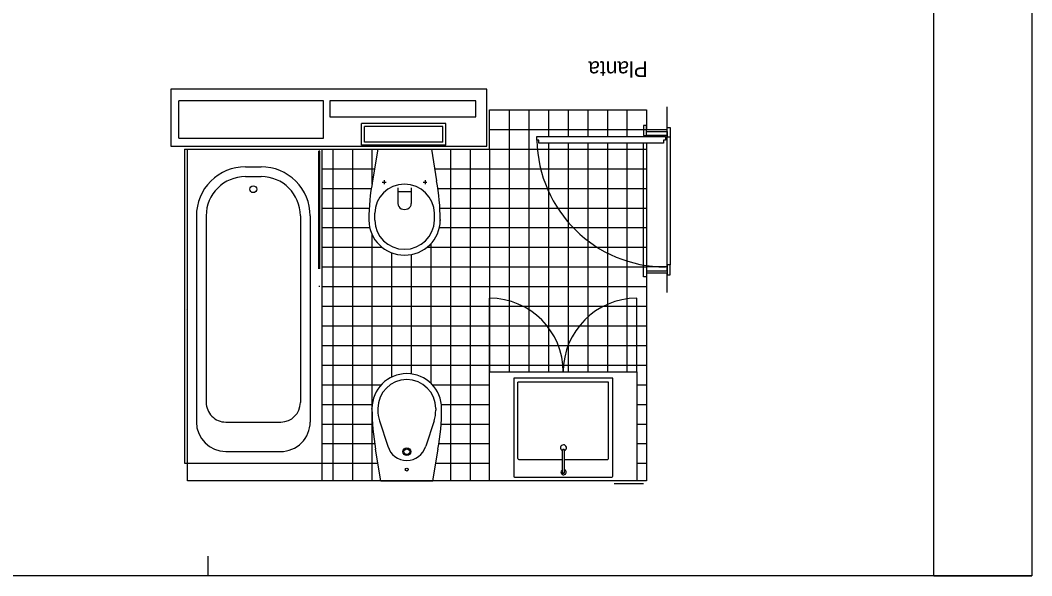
# Model space of a CAD drawing. Extents: x 1289.5 to 1301.1, y -287.4 to -281.5.
# Drawn here: x 1295.93 to 1301.09, y -287.45 to -284.62 of the extents above; entities that cross this region are included whole.
import ezdxf

# ---------------------------------------------------------------- set-up
doc = ezdxf.new("R2010")
doc.units = 0
for name, color, linetype in [('Level 1', 7, 'Continuous'), ('Level 10', 7, 'Continuous'), ('Level 11', 7, 'Continuous'), ('Level 13', 7, 'Continuous'), ('Level 2', 7, 'Continuous'), ('Level 36', 7, 'Continuous'), ('Level 4', 7, 'Continuous'), ('Level 60', 7, 'Continuous'), ('Level 62', 7, 'Continuous')]:
    doc.layers.add(name, color=color, linetype=linetype)

msp = doc.modelspace()

# ---------------------------------------------------------------- linework, layer by layer
at = {"layer": 'Level 1'}
for p, q in [((1298.3115, -284.9706), (1296.7015, -284.9706)), ((1296.7015, -284.9706), (1296.7015, -285.2606)), ((1298.3115, -285.2606), (1298.3115, -284.9706)), ((1296.7415, -285.2206), (1296.7415, -285.0306)), ((1297.4794, -285.0306), (1296.7415, -285.0306)), ((1297.4794, -285.2206), (1297.4794, -285.0306)), ((1297.5115, -285.0306), (1297.5115, -285.1106)), ((1298.2565, -285.0306), (1297.5115, -285.0306)), ((1298.2565, -285.1106), (1298.2565, -285.0306)), ((1298.3265, -285.2756), (1298.3265, -285.0756)), ((1298.3265, -285.0756), (1299.1265, -285.0756)), ((1299.1265, -285.0756), (1299.1265, -285.1756)), ((1299.2315, -285.1756), (1299.2315, -285.0606)), ((1297.5115, -285.1106), (1298.2565, -285.1106)), ((1299.1265, -285.1756), (1299.2315, -285.1756)), ((1296.7015, -285.2606), (1298.3115, -285.2606)), ((1296.7415, -285.2206), (1297.4794, -285.2206)), ((1296.7865, -286.9656), (1296.7865, -285.2756)), ((1296.7865, -285.2756), (1298.3265, -285.2756)), ((1299.1265, -285.9056), (1299.1265, -286.9656)), ((1299.1265, -285.9056), (1299.1365, -285.9056)), ((1299.1265, -285.9056), (1299.2315, -285.9056)), ((1299.2215, -285.9056), (1299.2315, -285.9056)), ((1299.2315, -286.0056), (1299.2315, -285.9056)), ((1299.1265, -286.9656), (1296.7865, -286.9656)), ((1299.1115, -286.9806), (1298.9615, -286.9806))]:
    msp.add_line(p, q, dxfattribs=at)
at = {"layer": 'Level 10'}
for p, q in [((1298.4265, -285.0756), (1298.4265, -286.4101)), ((1298.5265, -285.0756), (1298.5265, -286.4101)), ((1298.6265, -285.0756), (1298.6265, -285.2106)), ((1298.7265, -285.0756), (1298.7265, -285.2106)), ((1298.8265, -285.0756), (1298.8265, -285.2106)), ((1298.9265, -285.0756), (1298.9265, -285.2106)), ((1299.0265, -285.0756), (1299.0265, -285.2106)), ((1298.3265, -285.1756), (1299.1265, -285.1756)), ((1299.1265, -285.2056), (1299.1265, -285.2106)), ((1299.2315, -285.8756), (1299.2315, -285.2106)), ((1298.6265, -285.2456), (1298.6265, -286.4101)), ((1298.7265, -285.2456), (1298.7265, -286.4101)), ((1298.8265, -285.2456), (1298.8265, -286.4101)), ((1298.9265, -285.2456), (1298.9265, -286.4101)), ((1299.0265, -285.2456), (1299.0265, -286.4101)), ((1299.1265, -285.2456), (1299.1265, -285.8756)), ((1297.5265, -285.2756), (1297.5265, -286.9656)), ((1297.6265, -285.2756), (1297.6265, -286.9656)), ((1297.7265, -285.2756), (1297.7265, -285.4536)), ((1298.1265, -285.2756), (1298.1265, -286.9656)), ((1298.2265, -285.2756), (1298.2265, -286.9656)), ((1298.3265, -285.2756), (1298.3265, -286.4101)), ((1298.3265, -285.2756), (1299.1265, -285.2756)), ((1297.4715, -285.3756), (1297.7396, -285.3756)), ((1298.0457, -285.3756), (1299.1265, -285.3756)), ((1297.4715, -285.4756), (1297.7229, -285.4756)), ((1298.0624, -285.4756), (1299.1265, -285.4756)), ((1297.4715, -285.5756), (1297.7125, -285.5756)), ((1298.0728, -285.5756), (1299.1265, -285.5756)), ((1297.4715, -285.6756), (1297.7149, -285.6756)), ((1298.0704, -285.6756), (1299.1265, -285.6756)), ((1297.7265, -285.7102), (1297.7265, -286.9656)), ((1297.4715, -285.7756), (1297.7776, -285.7756)), ((1298.0078, -285.7756), (1299.1265, -285.7756)), ((1298.0265, -285.7584), (1298.0265, -286.468)), ((1297.8265, -285.8035), (1297.8265, -286.4371)), ((1297.9265, -285.8126), (1297.9265, -286.4206)), ((1297.4715, -285.8756), (1299.1265, -285.8756)), ((1297.4715, -285.9756), (1299.1265, -285.9756)), ((1297.4715, -286.0756), (1299.1265, -286.0756)), ((1297.4715, -286.1756), (1299.1265, -286.1756)), ((1297.4715, -286.2756), (1299.1265, -286.2756)), ((1297.4715, -286.3756), (1299.1265, -286.3756)), ((1297.4715, -286.4756), (1297.7745, -286.4756)), ((1298.034, -286.4756), (1298.3265, -286.4756)), ((1299.0765, -286.4756), (1299.1265, -286.4756)), ((1297.4715, -286.5756), (1297.727, -286.5756)), ((1298.0805, -286.5756), (1298.3265, -286.5756)), ((1299.0765, -286.5756), (1299.1265, -286.5756)), ((1297.4715, -286.6756), (1297.7293, -286.6756)), ((1298.0792, -286.6756), (1298.3265, -286.6756)), ((1299.0765, -286.6756), (1299.1265, -286.6756)), ((1297.4715, -286.7756), (1297.7405, -286.7756)), ((1298.0678, -286.7756), (1298.3265, -286.7756)), ((1299.0765, -286.7756), (1299.1265, -286.7756)), ((1297.4715, -286.8756), (1297.7572, -286.8756)), ((1298.0513, -286.8756), (1298.3265, -286.8756)), ((1299.0765, -286.8756), (1299.1265, -286.8756))]:
    msp.add_line(p, q, dxfattribs=at)
at = {"layer": 'Level 11'}
for p, q in [((1297.6733, -285.2556), (1297.6733, -285.1456)), ((1298.1033, -285.1456), (1297.6733, -285.1456)), ((1298.0883, -285.1606), (1297.6883, -285.1606)), ((1297.6883, -285.2406), (1297.6883, -285.1606)), ((1298.0883, -285.2406), (1298.0883, -285.1606)), ((1298.1033, -285.2556), (1298.1033, -285.1456)), ((1298.1033, -285.2556), (1297.6733, -285.2556)), ((1298.0883, -285.2406), (1297.6883, -285.2406)), ((1296.7715, -285.2756), (1296.7715, -286.8756)), ((1296.7715, -285.2756), (1297.4715, -285.2756)), ((1297.4715, -285.2756), (1297.4715, -286.8756)), ((1297.756, -285.2756), (1297.7294, -285.4376)), ((1297.756, -285.2756), (1298.0293, -285.2756)), ((1298.0293, -285.2756), (1298.0559, -285.4376)), ((1297.0815, -285.3656), (1297.1615, -285.3656)), ((1297.0815, -285.4156), (1297.1615, -285.4156)), ((1297.7783, -285.4438), (1297.7983, -285.4438)), ((1297.7883, -285.4338), (1297.7883, -285.4538)), ((1297.987, -285.4438), (1298.007, -285.4438)), ((1297.997, -285.4338), (1297.997, -285.4538)), ((1297.8583, -285.4736), (1297.8583, -285.5533)), ((1297.8583, -285.4913), (1297.927, -285.4913)), ((1297.927, -285.4736), (1297.927, -285.5534)), ((1296.8315, -285.6156), (1296.8315, -286.6656)), ((1296.8815, -285.6156), (1296.8815, -286.5656)), ((1297.3615, -285.6156), (1297.3615, -286.5656)), ((1297.4115, -285.6156), (1297.4115, -286.6656)), ((1297.7408, -285.6382), (1297.7408, -285.6021)), ((1298.0445, -285.6382), (1298.0445, -285.6021)), ((1297.7108, -285.6348), (1297.7108, -285.6385)), ((1298.0745, -285.6348), (1298.0745, -285.6385)), ((1298.4493, -286.442), (1298.4493, -286.9412)), ((1298.9537, -286.442), (1298.4493, -286.442)), ((1298.9537, -286.9412), (1298.9537, -286.442)), ((1298.4704, -286.8516), (1298.4704, -286.4631)), ((1298.9326, -286.4631), (1298.4704, -286.4631)), ((1298.9326, -286.8516), (1298.9326, -286.4631)), ((1297.7267, -286.6001), (1297.7267, -286.5964)), ((1297.7567, -286.5967), (1297.7567, -286.6048)), ((1298.0517, -286.5967), (1298.0517, -286.6048)), ((1298.0817, -286.6001), (1298.0817, -286.5964)), ((1296.9815, -286.6656), (1297.2615, -286.6656)), ((1297.7644, -286.6597), (1297.8081, -286.7889)), ((1298.0441, -286.6597), (1298.0004, -286.7889)), ((1297.7719, -286.9654), (1297.7453, -286.8034)), ((1298.0366, -286.9654), (1298.0632, -286.8034)), ((1298.6976, -286.9204), (1298.6976, -286.8109)), ((1298.7088, -286.9204), (1298.7088, -286.8109)), ((1296.9815, -286.8156), (1297.2615, -286.8156)), ((1298.4748, -286.8559), (1298.6976, -286.856)), ((1298.7088, -286.856), (1298.9282, -286.856)), ((1296.7715, -286.8756), (1297.4715, -286.8756)), ((1297.7719, -286.9654), (1298.0366, -286.9654)), ((1298.4537, -286.9455), (1298.9493, -286.9455))]:
    msp.add_line(p, q, dxfattribs=at)
for centre, radius in [((1297.1215, -285.48), 0.0173), ((1297.9042, -286.8166), 0.02), ((1297.9042, -286.8166), 0.0146), ((1297.9042, -286.9075), 0.00766)]:
    msp.add_circle(centre, radius, dxfattribs=at)
for centre, radius, start, end in [((1297.0815, -285.6156), 0.25, 89.9999, 179.9999), ((1297.1615, -285.6156), 0.25, 360, 90.0001), ((1297.0815, -285.6156), 0.2, 90, 180), ((1297.1615, -285.6156), 0.2, 360, 90), ((1297.9042, -286.5967), 0.1775, 0.0001, 179.9998), ((1297.9042, -286.5967), 0.1475, 0.0001, 179.9998), ((1296.9815, -286.5656), 0.1, 180, 270.0001), ((1297.2615, -286.5656), 0.1, 270.0001, 359.9999), ((1297.9567, -286.6048), 0.2, 179.9994, 195.9307), ((1297.8517, -286.6048), 0.2, 344.0681, 359.9983), ((1296.9815, -286.6656), 0.15, 180, 270), ((1297.2615, -286.6656), 0.15, 269.9999, 0.0002), ((1297.9042, -286.7615), 0.1, 195.8047, 344.0683), ((1298.7028, -286.7965), 0.015, 293.6307, 249.2833), ((1298.7032, -286.8103), 0.00566, 354.0176, 185.9962), ((1298.4748, -286.8516), 0.00438, 180, 270), ((1298.9282, -286.8516), 0.00438, 270, 0), ((1298.7036, -286.921), 0.0135, 116.7199, 67.3909), ((1298.4537, -286.9412), 0.00438, 180, 270), ((1298.7032, -286.921), 0.00566, 174.0038, 5.9824), ((1298.9493, -286.9412), 0.00438, 270, 0)]:
    msp.add_arc(centre, radius, start, end, dxfattribs=at)
for centre, major_axis, ratio, start_param, end_param in [((1299.1103, -285.6348), (-1.3994, 0), 0.868644, 6.120269, 6.283188), ((1297.8927, -285.6021), (0.1518, 0), 0.971435, 0.000003, 3.14159), ((1296.6739, -285.6348), (1.4006, 0), 0.867922, 6.283184, 6.446103), ((1297.8927, -285.5532), (0.0343, 0), 0.873689, 3.141584, 6.283207), ((1297.8927, -285.6382), (0.1818, 0), 0.976148, 3.141597, 6.283184), ((1297.8927, -285.6382), (0.1518, 0), 0.971435, 3.141597, 6.283184), ((1299.1267, -286.6001), (-1.4, 0), 0.895428, 6.283183, 6.446102), ((1296.6817, -286.6001), (1.4, 0), 0.895428, 6.120269, 6.283187)]:
    msp.add_ellipse(centre, major_axis=major_axis, ratio=ratio, start_param=start_param, end_param=end_param, dxfattribs=at)
at = {"layer": 'Level 13'}
for p, q in [((1299.1115, -285.1556), (1299.1115, -285.2056)), ((1299.1265, -285.1556), (1299.1115, -285.1556)), ((1299.1265, -285.2056), (1299.1265, -285.1556)), ((1298.5672, -285.2106), (1299.2222, -285.2106)), ((1298.5672, -285.2306), (1298.5672, -285.2106)), ((1299.1115, -285.2056), (1299.1265, -285.2056)), ((1299.1265, -285.1856), (1299.2315, -285.1856)), ((1299.1265, -285.2056), (1299.1265, -285.1856)), ((1299.2315, -285.2056), (1299.1265, -285.2056)), ((1299.2222, -285.2106), (1299.2222, -285.2306)), ((1299.2315, -285.2156), (1299.2315, -285.1656)), ((1299.2315, -285.1656), (1299.2465, -285.1656)), ((1299.2315, -285.1856), (1299.2315, -285.2156)), ((1299.2465, -285.1656), (1299.2465, -285.2156)), ((1298.5772, -285.2306), (1298.5674, -285.2306)), ((1298.5772, -285.2456), (1298.5772, -285.2306)), ((1299.2122, -285.2456), (1298.5772, -285.2456)), ((1299.2122, -285.2306), (1299.2122, -285.2456)), ((1299.2222, -285.2306), (1299.2122, -285.2306)), ((1299.2465, -285.2156), (1299.2315, -285.2156)), ((1299.1115, -285.9256), (1299.1115, -285.8756)), ((1299.1115, -285.8756), (1299.1265, -285.8756)), ((1299.2315, -285.8756), (1299.1265, -285.8756)), ((1299.1265, -285.8756), (1299.1265, -285.8956)), ((1299.1265, -285.8756), (1299.1265, -285.9256)), ((1299.2315, -285.8956), (1299.2315, -285.8656)), ((1299.2465, -285.8656), (1299.2315, -285.8656)), ((1299.2315, -285.8656), (1299.2315, -285.9156)), ((1299.2465, -285.9156), (1299.2465, -285.8656)), ((1299.1265, -285.9256), (1299.1115, -285.9256)), ((1299.1265, -285.8956), (1299.2315, -285.8956)), ((1299.2315, -285.9156), (1299.2465, -285.9156))]:
    msp.add_line(p, q, dxfattribs=at)
at = {"layer": 'Level 2'}
for p, q in [((1298.3265, -286.4101), (1299.0765, -286.4101)), ((1298.3265, -286.9656), (1298.3265, -286.4101)), ((1299.0765, -286.4101), (1299.0765, -286.9656)), ((1297.4715, -286.8756), (1297.4715, -286.9656))]:
    msp.add_line(p, q, dxfattribs=at)
at = {"layer": 'Level 36'}
for p, q in [((1297.455, -285.8856), (1297.455, -285.2856)), ((1297.46, -285.2856), (1297.455, -285.2856)), ((1297.46, -285.8856), (1297.46, -285.2856)), ((1297.46, -285.9756), (1297.455, -285.9756))]:
    msp.add_line(p, q, dxfattribs=at)
at = {"layer": 'Level 4'}
for p, q in [((1299.1115, -285.8756), (1299.1115, -285.2456)), ((1299.2465, -285.2156), (1299.2465, -285.8656)), ((1298.3265, -286.4101), (1298.3265, -286.0351)), ((1299.0765, -286.4101), (1299.0765, -286.0351))]:
    msp.add_line(p, q, dxfattribs=at)
for centre, start, end in [((1298.3265, -286.4101), 0, 89.9989), ((1299.0765, -286.4101), 90.0011, 180)]:
    msp.add_arc(centre, 0.375, start, end, dxfattribs=at)
msp.add_ellipse((1299.2222, -285.217), major_axis=(0, 0.6586), ratio=0.994272, start_param=1.591512, end_param=3.141593, dxfattribs=at)
at = {"layer": 'Level 62'}
for p, q in [((1300.5901, -287.4483), (1300.5901, -281.5083)), ((1296.7815, -286.0906), (1296.7815, -286.0906)), ((1296.8897, -287.3483), (1296.8897, -287.4483)), ((1300.5901, -287.4483), (1301.0901, -287.4483))]:
    msp.add_line(p, q, dxfattribs=at)
msp.add_lwpolyline([(1301.0901, -281.5083), (1301.0901, -287.4483), (1289.4905, -287.4483), (1289.4905, -281.5083)], close=True, dxfattribs=at)

# ---------------------------------------------------------------- texts
at = {"layer": 'Level 60'}
msp.add_text('Planta', height=0.08, rotation=180, dxfattribs=at).set_placement((1299.1324, -284.8284))

doc.saveas('drawing.dxf')
